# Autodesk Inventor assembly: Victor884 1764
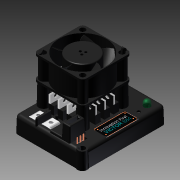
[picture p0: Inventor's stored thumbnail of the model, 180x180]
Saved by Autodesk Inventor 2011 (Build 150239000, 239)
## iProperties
Shininess: 64.0
Length Units: 11272
Angle Units: 11279
Time Units: 11290
Mass Units: 11286
Length Display Precision: 3
Angle Display Precision: 2
Compacted: True
Part Number: Victor884 1764
Document SubType Name: Assembly
Created: 2007-01
Designer: uidk0133
Density: 0.0
Volumn: 0.0
Area: 0.0
PropertySet Name: Model Information
Control State: 0
Master: False
Checked Out: False
Author: uidk0133
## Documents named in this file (9)
- R:\CAD Archives\Electronics\Victor 884 1764\Victor884 1764.iam
- R:\CAD Archives\Electronics\Victor 884 1764\Victor Cover 1764.ipt
- R:\CAD Archives\Electronics\Victor 884 1764\Victor Fan 1764.ipt
- R:\CAD Archives\Electronics\Victor 884 1764\Victor Base 1764.ipt
- R:\CAD Archives\Electronics\Victor 884 1764\Victor Capacitor 1764.ipt
- R:\CAD Archives\Electronics\Victor 884 1764\Victor LED Green 1764.ipt
- R:\CAD Archives\Electronics\Victor 884 1764\Victor Fet 1764.ipt
- R:\CAD Archives\Electronics\Victor 884 1764\Victor Screw Terminal 1764.ipt
- R:\CAD Archives\Electronics\Victor 884 1764\Victor 3 Pin Connector 1764.ipt
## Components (22 placed, 8 different names)
1. Victor Cover 1764:1 — Mate:1, Mate:2, Mate:3, Mate:4, Mate:5, Angle:1, Mate:6, Mate:7, Mate:8, Mate:9, Flush:2, Flush:3, Flush:4, Flush:9, Flush:13, Mate:12
2. Victor Fan 1764:1 — Mate:4, Mate:5, Angle:1, Flush:1, Flush:10, Mate:10, Mate:13, Mate:14
3. Victor Base 1764:1 — Mate:1, Mate:2, Mate:3
4. Victor Capacitor 1764:1 — Mate:6, Flush:13
5. Victor LED Green 1764:1 — Mate:7, Mate:8
6. Victor 3 Pin Connector 1764:1 — Mate:12, Mate:13, Mate:14
7. Victor Fet 1764:14 — Flush:3, Flush:6, Flush:8
8. Victor Fet 1764:15 — Flush:4, Flush:5, Flush:7, Flush:8
9. Victor Fet 1764:13 — Mate:9, Flush:1, Flush:2, Flush:5, Flush:6, Flush:7
10. Victor Fet 1764:16
11. Victor Fet 1764:17
12. Victor Fet 1764:18
13. Victor Fet 1764:19
14. Victor Fet 1764:20
15. Victor Fet 1764:21
16. Victor Fet 1764:22
17. Victor Fet 1764:23
18. Victor Fet 1764:24
19. Victor Screw Terminal 1764:5 — Flush:9, Flush:10, Mate:10, Flush:11, Flush:12, Mate:11
20. Victor Screw Terminal 1764:6 — Flush:11, Flush:12, Mate:11
21. Victor Screw Terminal 1764:7
22. Victor Screw Terminal 1764:8
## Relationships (28: Mate 14, Flush 13, Angle 1)
- Mate:1: Victor Cover 1764:1 ↔ Victor Base 1764:1
- Mate:2: Victor Cover 1764:1 ↔ Victor Base 1764:1
- Mate:3: Victor Cover 1764:1 ↔ Victor Base 1764:1
- Mate:4: Victor Cover 1764:1 ↔ Victor Fan 1764:1
- Mate:5: Victor Cover 1764:1 ↔ Victor Fan 1764:1
- Angle:1: Victor Cover 1764:1 ↔ Victor Fan 1764:1
- Mate:6: Victor Cover 1764:1 ↔ Victor Capacitor 1764:1
- Mate:7: Victor Cover 1764:1 ↔ Victor LED Green 1764:1
- Mate:8: Victor Cover 1764:1 ↔ Victor LED Green 1764:1
- Mate:9: Victor Cover 1764:1 ↔ Victor Fet 1764:13
- Flush:1: Victor Fan 1764:1 ↔ Victor Fet 1764:13
- Flush:2: Victor Cover 1764:1 ↔ Victor Fet 1764:13
- Flush:3: Victor Cover 1764:1 ↔ Victor Fet 1764:14
- Flush:4: Victor Cover 1764:1 ↔ Victor Fet 1764:15
- Flush:5: Victor Fet 1764:15 ↔ Victor Fet 1764:13
- Flush:6: Victor Fet 1764:14 ↔ Victor Fet 1764:13
- Flush:7: Victor Fet 1764:15 ↔ Victor Fet 1764:13
- Flush:8: Victor Fet 1764:14 ↔ Victor Fet 1764:15
- Flush:9: Victor Cover 1764:1 ↔ Victor Screw Terminal 1764:5
- Flush:10: Victor Fan 1764:1 ↔ Victor Screw Terminal 1764:5
- Mate:10: Victor Fan 1764:1 ↔ Victor Screw Terminal 1764:5
- Flush:11: Victor Screw Terminal 1764:5 ↔ Victor Screw Terminal 1764:6
- Flush:12: Victor Screw Terminal 1764:5 ↔ Victor Screw Terminal 1764:6
- Mate:11: Victor Screw Terminal 1764:5 ↔ Victor Screw Terminal 1764:6
- Flush:13: Victor Cover 1764:1 ↔ Victor Capacitor 1764:1
- Mate:12: Victor Cover 1764:1 ↔ Victor 3 Pin Connector 1764:1
- Mate:13: Victor Fan 1764:1 ↔ Victor 3 Pin Connector 1764:1
- Mate:14: Victor Fan 1764:1 ↔ Victor 3 Pin Connector 1764:1
